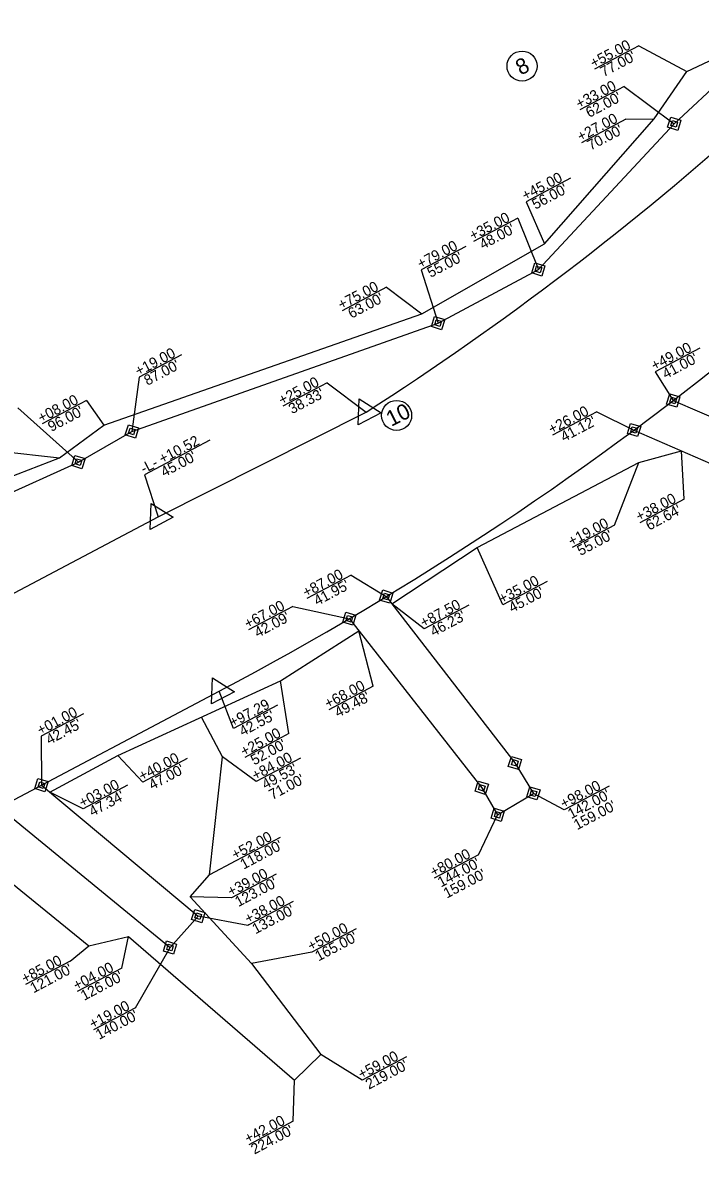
# Model space of a CAD drawing. Extents: x 1487704 to 1489071, y 498271 to 499440.
# Drawn here: x 1488029 to 1488354, y 498271 to 498813 of the extents above; entities that cross this region are included whole.
import ezdxf

# ---------------------------------------------------------------- set-up
doc = ezdxf.new("R2010")
doc.units = 0
for name, color, linetype in [('Prop Easement Construction', 7, 'Continuous'), ('Prop Easement Construction Station Offsets', 7, 'Continuous'), ('Prop Easement Permanent Drainage', 7, 'Continuous'), ('Prop Easement Permanent Drainage Station Offsets', 7, 'Continuous'), ('Prop Easement Temporary Drainage', 7, 'Continuous'), ('Prop Easement Temporary Drainage Station Offsets', 7, 'Continuous'), ('Prop ROW Marker CELL', 7, 'Continuous'), ('Prop ROW Permanent Easement CELL', 7, 'Continuous'), ('Prop ROW RW Lines', 7, 'Continuous'), ('Prop ROW Station Offsets', 7, 'Continuous'), ('Prop ROW Text', 7, 'Continuous')]:
    doc.layers.add(name, color=color, linetype=linetype)

msp = doc.modelspace()

# ---------------------------------------------------------------- linework, layer by layer
at = {"layer": 'Prop Easement Construction'}
for p, q in [((1488324.13, 498601.89), (1488344.57, 498607.45)), ((1488246.81, 498561.13), (1488324.13, 498601.89)), ((1488205.84, 498534.27), (1488246.81, 498561.13)), ((1488152.59, 498497.29), (1488190.15, 498521.26)), ((1488074.71, 498461.64), (1488152.59, 498497.29)), ((1488042.17, 498444.03), (1488074.71, 498461.64))]:
    msp.add_line(p, q, dxfattribs=at)
at = {"layer": 'Prop Easement Construction Station Offsets'}
for p, q in [((1488345.96, 498584.32), (1488324.69, 498573.09)), ((1488312.54, 498571.92), (1488292.34, 498561.25)), ((1488280.3, 498544.95), (1488259.03, 498533.72)), ((1488242.72, 498533.54), (1488221.45, 498522.31)), ((1488196.92, 498494.78), (1488175.66, 498483.55)), ((1488156.62, 498472.08), (1488135.48, 498460.62)), ((1488107.92, 498460.12), (1488086.67, 498448.87)), ((1488079.28, 498447.36), (1488058.03, 498436.11))]:
    msp.add_line(p, q, dxfattribs=at)
for points in [[(1488345.92, 498584.39), (1488344.57, 498607.45), (1488344.57, 498607.45)], [(1488312.54, 498571.92), (1488324.13, 498601.89), (1488324.13, 498601.89)], [(1488259.03, 498533.72), (1488246.81, 498561.13), (1488246.81, 498561.13)], [(1488221.45, 498522.31), (1488205.84, 498534.27), (1488205.84, 498534.27)], [(1488196.92, 498494.78), (1488190.15, 498521.26), (1488190.15, 498521.26)], [(1488156.62, 498472.08), (1488152.59, 498497.29)], [(1488086.67, 498448.87), (1488074.71, 498461.64)], [(1488058.03, 498436.11), (1488042.17, 498444.03)]]:
    msp.add_lwpolyline(points, dxfattribs=at)
at = {"layer": 'Prop Easement Permanent Drainage'}
for p, q in [((1488341.17, 498764.08), (1488411.92, 498830)), ((1488276.08, 498694.39), (1488341.17, 498764.08)), ((1488228.03, 498668.68), (1488276.08, 498694.39)), ((1488081.39, 498616.82), (1488228.03, 498668.68)), ((1488340.67, 498631.59), (1488396.25, 498607.56)), ((1488321.79, 498617.36), (1488388.08, 498588.53)), ((1488055.79, 498602.11), (1488081.39, 498616.82)), ((1487994.71, 498574.3), (1488055.79, 498602.11)), ((1488203.21, 498537.68), (1488264.86, 498458.03)), ((1488185.55, 498527.13), (1488248.96, 498446.16)), ((1488264.86, 498458.03), (1488273.69, 498443.5)), ((1488038.11, 498447.42), (1488113.18, 498384.7)), ((1488248.96, 498446.16), (1488256.59, 498433.25)), ((1488256.59, 498433.25), (1488273.69, 498443.5)), ((1488017.78, 498436.68), (1488099.66, 498369.62)), ((1488099.66, 498369.62), (1488113.18, 498384.7))]:
    msp.add_line(p, q, dxfattribs=at)
at = {"layer": 'Prop Easement Permanent Drainage Station Offsets'}
for p, q in [((1488317.25, 498781.95), (1488295.98, 498770.72)), ((1488266.28, 498718.87), (1488245.02, 498707.64)), ((1488241.29, 498705.35), (1488220.02, 498694.13)), ((1488353.35, 498656.61), (1488332.08, 498645.38)), ((1488105.12, 498653.41), (1488084.92, 498642.74)), ((1488304.11, 498626.17), (1488282.84, 498614.95)), ((1488186.45, 498548.01), (1488165.19, 498536.78)), ((1488158.48, 498533.03), (1488137.21, 498521.8)), ((1488058.16, 498481.5), (1488037.95, 498470.83)), ((1488309.97, 498446.92), (1488288.44, 498435.55)), ((1488247.47, 498414.12), (1488226.21, 498402.89)), ((1488158.66, 498391.72), (1488137.4, 498380.49)), ((1488083.19, 498340.86), (1488062.99, 498330.19))]:
    msp.add_line(p, q, dxfattribs=at)
for points in [[(1488317.25, 498781.95), (1488341.17, 498764.08)], [(1488266.28, 498718.87), (1488276.08, 498694.39)], [(1488220.02, 498694.13), (1488228.03, 498668.68)], [(1488332.08, 498645.38), (1488340.65, 498631.57), (1488340.67, 498631.59)], [(1488084.92, 498642.74), (1488081.39, 498616.82)], [(1488026.73, 498628.03), (1488055.79, 498602.11)], [(1488304.11, 498626.17), (1488321.8, 498617.35), (1488321.79, 498617.36)], [(1488186.45, 498548.01), (1488203.21, 498537.68), (1488203.21, 498537.68)], [(1488158.48, 498533.03), (1488185.55, 498527.13), (1488185.55, 498527.13)], [(1488037.95, 498470.83), (1488038.11, 498447.42), (1488038.11, 498447.42)], [(1488288.41, 498435.62), (1488273.69, 498443.5), (1488273.69, 498443.5)], [(1488247.47, 498414.12), (1488256.59, 498433.25), (1488256.59, 498433.25)], [(1488137.4, 498380.49), (1488136.9, 498380.23), (1488113.18, 498384.7)], [(1488083.19, 498340.86), (1488099.66, 498369.62), (1488099.66, 498369.62)]]:
    msp.add_lwpolyline(points, dxfattribs=at)
at = {"layer": 'Prop Easement Temporary Drainage'}
for p, q in [((1488347.21, 498789.14), (1488369.59, 498799.74)), ((1488331.62, 498766.47), (1488347.21, 498789.14)), ((1488279.01, 498706.57), (1488331.62, 498766.47)), ((1488220.34, 498673.12), (1488279.01, 498706.57)), ((1488067.91, 498619.84), (1488220.34, 498673.12)), ((1488046.8, 498604.14), (1488067.91, 498619.84)), ((1487992.26, 498583.19), (1488046.8, 498604.14)), ((1488124.83, 498461.01), (1488114.79, 498479.99)), ((1488118.54, 498404.5), (1488124.83, 498461.01)), ((1488011.14, 498410.74), (1488060.72, 498370.51)), ((1488109.38, 498394), (1488118.54, 498404.5)), ((1488109.38, 498394), (1488138.76, 498362.03)), ((1488060.72, 498370.51), (1488079.86, 498374.98)), ((1488079.86, 498374.98), (1488159.29, 498306.14)), ((1488138.76, 498362.03), (1488171.97, 498318.51)), ((1488159.29, 498306.14), (1488171.97, 498318.51))]:
    msp.add_line(p, q, dxfattribs=at)
at = {"layer": 'Prop Easement Temporary Drainage Station Offsets'}
for p, q in [((1488324.16, 498801.46), (1488302.89, 498790.23)), ((1488317.95, 498766.26), (1488296.68, 498755.03)), ((1488291.47, 498738.02), (1488270.2, 498726.79)), ((1488203.38, 498685.78), (1488182.11, 498674.55)), ((1488059.63, 498631.57), (1488038.36, 498620.35)), ((1488162.14, 498460.37), (1488140.87, 498449.14)), ((1488152.41, 498422.39), (1488131.15, 498411.16)), ((1488150.43, 498404.74), (1488129.16, 498393.51)), ((1488188.81, 498378.7), (1488167.55, 498367.47)), ((1488051.77, 498363.15), (1488030.51, 498351.92)), ((1488076.54, 498359.83), (1488055.27, 498348.6)), ((1488212.96, 498317.34), (1488191.7, 498306.11)), ((1488158.62, 498286.5), (1488137.35, 498275.27))]:
    msp.add_line(p, q, dxfattribs=at)
for points in [[(1488324.16, 498801.46), (1488347.21, 498789.14)], [(1488317.95, 498766.26), (1488331.62, 498766.47)], [(1488270.2, 498726.79), (1488279.01, 498706.57)], [(1488203.38, 498685.78), (1488220.34, 498673.12), (1488220.34, 498673.12)], [(1488059.63, 498631.57), (1488067.91, 498619.84)], [(1488018.02, 498607.38), (1488046.8, 498604.14)], [(1488140.87, 498449.14), (1488124.83, 498461.01)], [(1488131.15, 498411.16), (1488118.54, 498404.5)], [(1488129.16, 498393.51), (1488109.38, 498394)], [(1488076.54, 498359.83), (1488079.86, 498374.98)], [(1488051.77, 498363.15), (1488060.72, 498370.51)], [(1488167.55, 498367.47), (1488138.76, 498362.03), (1488138.76, 498362.03)], [(1488191.7, 498306.11), (1488171.97, 498318.51), (1488171.97, 498318.51)], [(1488158.62, 498286.5), (1488159.29, 498306.14), (1488159.29, 498306.14)]]:
    msp.add_lwpolyline(points, dxfattribs=at)
at = {"layer": 'Prop ROW Marker CELL'}
for p, q in [((1488341.17, 498764.08), (1488341.17, 498764.08)), ((1488276.08, 498694.39), (1488276.08, 498694.39)), ((1488228.03, 498668.68), (1488228.03, 498668.68)), ((1488340.67, 498631.59), (1488340.67, 498631.59)), ((1488193.54, 498625.99), (1488193.54, 498625.99)), ((1488321.92, 498617.46), (1488321.92, 498617.46)), ((1488081.39, 498616.82), (1488081.39, 498616.82)), ((1488055.79, 498602.11), (1488055.79, 498602.11)), ((1488093.99, 498575.94), (1488093.99, 498575.94)), ((1488203.21, 498537.68), (1488203.21, 498537.68)), ((1488185.55, 498527.13), (1488185.55, 498527.13)), ((1488123.33, 498492.41), (1488123.33, 498492.41)), ((1488264.86, 498458.03), (1488264.86, 498458.03)), ((1488038.11, 498447.42), (1488038.11, 498447.42)), ((1488248.96, 498446.16), (1488248.96, 498446.16)), ((1488273.69, 498443.5), (1488273.69, 498443.5)), ((1488256.59, 498433.25), (1488256.59, 498433.25)), ((1488113.18, 498384.7), (1488113.18, 498384.7)), ((1488099.66, 498369.62), (1488099.66, 498369.62))]:
    msp.add_line(p, q, dxfattribs=at)
for points in [[(1488189.7, 498619.89), (1488190.18, 498632.36), (1488200.75, 498625.72)], [(1488090.15, 498569.84), (1488090.63, 498582.31), (1488101.2, 498575.68)], [(1488119.49, 498486.31), (1488119.97, 498498.78), (1488130.54, 498492.15)]]:
    msp.add_lwpolyline(points, close=True, dxfattribs=at)
at = {"layer": 'Prop ROW Permanent Easement CELL'}
for points in [[(1488339.48, 498767.26), (1488344.35, 498765.76), (1488342.85, 498760.9), (1488337.98, 498762.4)], [(1488340.32, 498765.67), (1488342.76, 498764.92), (1488342.01, 498762.49), (1488339.57, 498763.24)], [(1488274.39, 498697.57), (1488279.26, 498696.07), (1488277.76, 498691.2), (1488272.89, 498692.71)], [(1488275.24, 498695.98), (1488277.67, 498695.23), (1488276.92, 498692.79), (1488274.48, 498693.55)], [(1488226.35, 498671.86), (1488231.21, 498670.36), (1488229.71, 498665.5), (1488224.84, 498667)], [(1488227.19, 498670.27), (1488229.62, 498669.52), (1488228.87, 498667.09), (1488226.44, 498667.84)], [(1488338.99, 498634.77), (1488343.85, 498633.27), (1488342.35, 498628.4), (1488337.48, 498629.9)], [(1488339.83, 498633.18), (1488342.26, 498632.43), (1488341.51, 498629.99), (1488339.08, 498630.75)], [(1488079.71, 498620), (1488084.57, 498618.5), (1488083.07, 498613.63), (1488078.2, 498615.14)], [(1488080.55, 498618.41), (1488082.98, 498617.66), (1488082.23, 498615.23), (1488079.8, 498615.98)], [(1488320.24, 498620.64), (1488325.1, 498619.14), (1488323.6, 498614.28), (1488318.73, 498615.78)], [(1488321.08, 498619.05), (1488323.51, 498618.3), (1488322.76, 498615.87), (1488320.33, 498616.62)], [(1488054.11, 498605.29), (1488058.98, 498603.79), (1488057.47, 498598.93), (1488052.61, 498600.43)], [(1488054.95, 498603.7), (1488057.39, 498602.95), (1488056.63, 498600.52), (1488054.2, 498601.27)], [(1488201.53, 498540.86), (1488206.39, 498539.36), (1488204.89, 498534.5), (1488200.02, 498536)], [(1488202.37, 498539.27), (1488204.8, 498538.52), (1488204.05, 498536.09), (1488201.62, 498536.84)], [(1488183.87, 498530.31), (1488188.73, 498528.81), (1488187.23, 498523.94), (1488182.37, 498525.44)], [(1488184.71, 498528.72), (1488187.14, 498527.97), (1488186.39, 498525.53), (1488183.96, 498526.29)], [(1488263.18, 498461.21), (1488268.05, 498459.71), (1488266.54, 498454.84), (1488261.68, 498456.34)], [(1488264.02, 498459.62), (1488266.45, 498458.87), (1488265.7, 498456.43), (1488263.27, 498457.19)], [(1488036.43, 498450.6), (1488041.3, 498449.1), (1488039.79, 498444.23), (1488034.93, 498445.74)], [(1488247.28, 498449.34), (1488252.14, 498447.84), (1488250.64, 498442.97), (1488245.77, 498444.48)], [(1488037.27, 498449.01), (1488039.71, 498448.26), (1488038.95, 498445.82), (1488036.52, 498446.58)], [(1488248.12, 498447.75), (1488250.55, 498447), (1488249.8, 498444.57), (1488247.36, 498445.32)], [(1488272.01, 498446.68), (1488276.88, 498445.18), (1488275.37, 498440.32), (1488270.51, 498441.82)], [(1488272.85, 498445.09), (1488275.28, 498444.34), (1488274.53, 498441.91), (1488272.1, 498442.66)], [(1488254.91, 498436.43), (1488259.77, 498434.93), (1488258.27, 498430.06), (1488253.41, 498431.56)], [(1488255.75, 498434.84), (1488258.18, 498434.09), (1488257.43, 498431.65), (1488255, 498432.41)], [(1488111.5, 498387.88), (1488116.36, 498386.38), (1488114.86, 498381.51), (1488110, 498383.02)], [(1488112.34, 498386.29), (1488114.77, 498385.54), (1488114.02, 498383.11), (1488111.59, 498383.86)], [(1488097.98, 498372.8), (1488102.85, 498371.3), (1488101.34, 498366.44), (1488096.48, 498367.94)], [(1488098.82, 498371.21), (1488101.25, 498370.46), (1488100.5, 498368.03), (1488098.07, 498368.78)]]:
    msp.add_lwpolyline(points, close=True, dxfattribs=at)
at = {"layer": 'Prop ROW RW Lines'}
for p, q in [((1488093.99, 498575.94), (1488193.54, 498625.99)), ((1487982.15, 498516.73), (1488093.99, 498575.94)), ((1487949.84, 498400.81), (1488123.26, 498492.38))]:
    msp.add_line(p, q, dxfattribs=at)
for centre, radius, start, end in [((1487403.1, 499856.48), 1462.5, 302.71583, 321.11571), ((1487403.1, 499856.44), 1542.5, 297.83218, 321.11298)]:
    msp.add_arc(centre, radius, start, end, dxfattribs=at)
at = {"layer": 'Prop ROW Station Offsets'}
for p, q in [((1488174.91, 498640.05), (1488153.64, 498628.82)), ((1488118.69, 498612.52), (1488087.42, 498596.01)), ((1488151.21, 498485.75), (1488130.05, 498474.57))]:
    msp.add_line(p, q, dxfattribs=at)
for points in [[(1488174.91, 498640.05), (1488193.54, 498625.99), (1488193.54, 498625.99)], [(1488087.42, 498596.01), (1488093.99, 498575.94), (1488093.99, 498575.94)], [(1488130.05, 498474.57), (1488123.26, 498492.38)]]:
    msp.add_lwpolyline(points, dxfattribs=at)
at = {"layer": 'Prop ROW Text'}
for p, q in [((1488268.27, 498791.69), (1488268.27, 498791.69)), ((1488208.19, 498624.44), (1488208.19, 498624.44))]:
    msp.add_line(p, q, dxfattribs=at)
for centre in [(1488268.27, 498791.69), (1488208.19, 498624.44)]:
    msp.add_circle(centre, 7.2, dxfattribs=at)

# ---------------------------------------------------------------- texts
at = {"layer": 'Prop Easement Construction Station Offsets'}
for s, rotation, p in [('+38.00', 27.8351, (1488324.33, 498573.47)), ("62.64'", 27.8351, (1488329.15, 498569.23)), ('+19.00', 27.8351, (1488291.97, 498561.63)), ("55.00'", 27.8351, (1488296.27, 498557.11)), ('+35.00', 27.8351, (1488258.67, 498534.1)), ("45.00'", 27.8351, (1488263.49, 498529.86)), ('+87.50', 27.8351, (1488221.09, 498522.68)), ("46.23'", 27.8351, (1488225.91, 498518.45)), ('+68.00', 27.8351, (1488175.3, 498483.93)), ("49.48'", 27.8351, (1488180.12, 498479.69)), ('+25.00', 28.4575, (1488135.11, 498460.99)), ("52.00'", 28.4575, (1488139.98, 498456.81)), ('+40.00', 27.895, (1488086.3, 498449.25)), ("47.00'", 27.895, (1488091.13, 498445.01)), ('+03.00', 27.895, (1488057.66, 498436.48)), ("47.34'", 27.895, (1488062.49, 498432.25))]:
    msp.add_text(s, height=5, rotation=rotation, dxfattribs=at).set_placement(p)
at = {"layer": 'Prop Easement Permanent Drainage Station Offsets'}
for s, p in [('+33.00', (1488295.62, 498771.09)), ("62.00'", (1488300.44, 498766.85)), ('+35.00', (1488244.65, 498708.01)), ("48.00'", (1488249.48, 498703.77)), ('+79.00', (1488219.66, 498694.5)), ("55.00'", (1488224.48, 498690.26)), ('+19.00', (1488084.55, 498643.12)), ('+49.00', (1488331.72, 498645.75)), ("87.00'", (1488088.85, 498638.6)), ("41.00'", (1488337.07, 498641.79)), ('+26.00', (1488282.48, 498615.32)), ("41.12'", (1488288.36, 498611.64)), ('+87.00', (1488164.83, 498537.16)), ("41.95'", (1488170.18, 498533.2)), ('+67.00', (1488136.85, 498522.17)), ("42.09'", (1488141.67, 498517.93)), ('+01.00', (1488037.59, 498471.2)), ("42.45'", (1488041.88, 498466.68)), ('+98.00', (1488288.21, 498436)), ("142.00'", (1488291.82, 498431.11)), ("159.00'", (1488294.62, 498425.81)), ('+80.00', (1488225.84, 498403.27)), ("144.00'", (1488229.45, 498398.38)), ("159.00'", (1488232.25, 498393.08)), ('+38.00', (1488137.04, 498380.87)), ("133.00'", (1488140.64, 498375.98)), ('+19.00', (1488062.62, 498330.57)), ("140.00'", (1488065.7, 498325.41))]:
    msp.add_text(s, height=5, rotation=27.8351, dxfattribs=at).set_placement(p)
at = {"layer": 'Prop Easement Temporary Drainage Station Offsets'}
for s, p in [('+55.00', (1488302.53, 498790.6)), ("77.00'", (1488307.35, 498786.36)), ('+27.00', (1488296.32, 498755.41)), ("70.00'", (1488301.14, 498751.17)), ('+45.00', (1488269.84, 498727.16)), ("56.00'", (1488274.66, 498722.92)), ('+75.00', (1488181.75, 498674.93)), ("63.00'", (1488186.57, 498670.69)), ('+08.00', (1488038, 498620.72)), ("96.00'", (1488042.82, 498616.48)), ('+84.00', (1488140.51, 498449.52)), ("49.53'", (1488145.33, 498445.28)), ("71.00'", (1488148.66, 498440.25)), ('+52.00', (1488130.79, 498411.54)), ("118.00'", (1488134.92, 498406.93)), ('+39.00', (1488128.8, 498393.88)), ("123.00'", (1488132.4, 498389)), ('+50.00', (1488167.18, 498367.84)), ("165.00'", (1488170.79, 498362.96)), ('+85.00', (1488030.14, 498352.29)), ('+04.00', (1488054.91, 498348.98)), ("121.00'", (1488034.28, 498347.69)), ("126.00'", (1488058.51, 498344.09)), ('+59.00', (1488191.34, 498306.48)), ("219.00'", (1488194.94, 498301.6)), ('+42.00', (1488136.99, 498275.64)), ("224.00'", (1488140.06, 498270.48))]:
    msp.add_text(s, height=5, rotation=27.8351, dxfattribs=at).set_placement(p)
at = {"layer": 'Prop ROW Station Offsets'}
for s, p in [('+25.00', (1488153.28, 498629.2)), ("38.33'", (1488158.1, 498624.96)), ('-L- +10.52', (1488087.13, 498596.42)), ("45.00'", (1488096.88, 498594.78)), ('+97.29', (1488129.67, 498474.94)), ("42.55'", (1488134.45, 498470.68))]:
    msp.add_text(s, height=5, rotation=27.8351, dxfattribs=at).set_placement(p)
at = {"layer": 'Prop ROW Text'}
for s, rotation, p in [('8', 27.4432, (1488267.62, 498787.12)), ('10', 26.9139, (1488205.6, 498618.92))]:
    msp.add_text(s, height=7.5, rotation=rotation, dxfattribs=at).set_placement(p)

doc.saveas('drawing.dxf')
